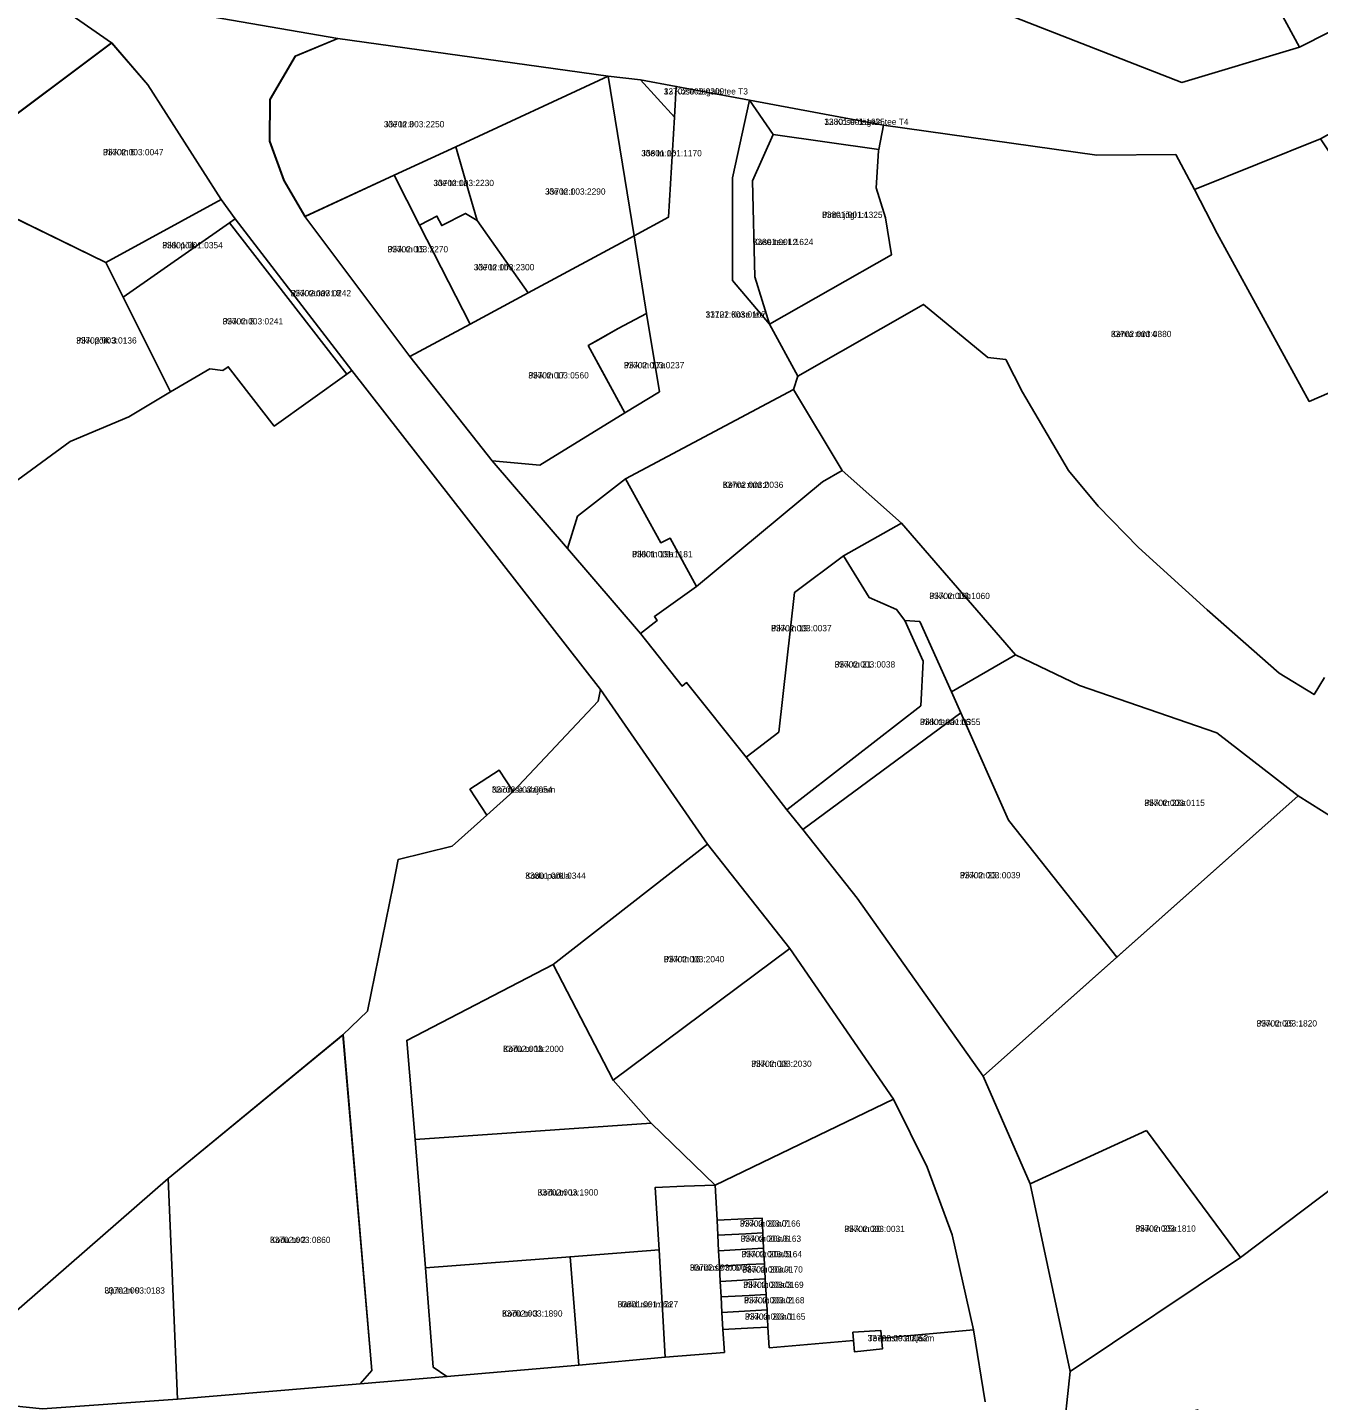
# Model space of a CAD drawing. Extents: x 551583 to 585220, y 6539942 to 6568852.
# Drawn here: x 566505.1 to 566814.5, y 6561149.5 to 6561478.7 of the extents above; entities that cross this region are included whole.
import ezdxf

# ---------------------------------------------------------------- set-up
doc = ezdxf.new("R2010")
doc.units = 0
for name, color, linetype in [('L_AADRESS', 7, 'Continuous'), ('PIIR', 7, 'Continuous'), ('TUNNUS', 7, 'Continuous')]:
    doc.layers.add(name, color=color, linetype=linetype)

msp = doc.modelspace()

# ---------------------------------------------------------------- linework, layer by layer
at = {"layer": 'PIIR'}
for points in [[(566791.18, 6561508.65), (566842.94, 6561542.25), (566867.01, 6561508.04), (566866.2, 6561503.29), (566839.93, 6561486.97), (566838.87, 6561488.68), (566809.96, 6561473.95)], [(566765.56, 6561529.79), (566776.67, 6561535.03), (566779.22, 6561530.74), (566791.18, 6561508.65), (566809.96, 6561473.95), (566781.7, 6561465.52), (566741.82, 6561481.07), (566731.29, 6561513.47)], [(566373.31, 6561508.62), (566505.33, 6561488.91), (566525.21, 6561475.01), (566494.84, 6561452.29), (566498.01, 6561445.37), (566497.1, 6561435.34), (566491.17, 6561435.81), (566484.69, 6561436.37), (566485.75, 6561446.39), (566479.83, 6561446.85), (566479.41, 6561443.1), (566466.6, 6561444.48), (566465.78, 6561437.06), (566427.68, 6561430.79), (566384.18, 6561428.7), (566375.88, 6561481.71), (566373.35, 6561504.49)], [(566579.42, 6561476.07), (566644.26, 6561466.97), (566607.74, 6561450.09), (566592.92, 6561443.25), (566571.62, 6561433.4), (566566.56, 6561442.03), (566563.14, 6561451.42), (566563.2, 6561461.42), (566569.28, 6561471.83)], [(566525.27, 6561475), (566533.92, 6561464.91), (566551.45, 6561437.4), (566523.81, 6561422.34), (566497.12, 6561435.35), (566498.05, 6561445.36), (566494.86, 6561452.26)], [(566607.74, 6561450.09), (566644.26, 6561466.97), (566650.48, 6561428.75), (566625.05, 6561415.05), (566612.84, 6561432.38), (566610.95, 6561438.97)], [(566644.26, 6561466.97), (566651.97, 6561466.15), (566660.11, 6561457.14), (566658.66, 6561433.18), (566650.48, 6561428.75)], [(566651.97, 6561466.15), (566660.57, 6561464.53), (566660.11, 6561457.14)], [(566634.52, 6561353.75), (566616.46, 6561374.76), (566627.86, 6561373.76), (566648.25, 6561386.29), (566656.51, 6561391.36), (566653.46, 6561410.12), (566650.48, 6561428.75), (566658.66, 6561433.18), (566660.11, 6561457.14), (566660.57, 6561464.53), (566678.07, 6561461.27), (566674, 6561442.65), (566674, 6561417.99), (566682.88, 6561407.58), (566689.67, 6561395.08), (566688.67, 6561391.93), (566648.38, 6561370.48), (566636.89, 6561361.49)], [(566678.07, 6561461.27), (566683.77, 6561453.02), (566678.86, 6561441.88), (566679.37, 6561418.92), (566682.88, 6561407.58), (566674, 6561417.99), (566674, 6561442.65)], [(566678.07, 6561461.27), (566710.22, 6561455.27), (566709.08, 6561449.39), (566683.77, 6561453.02)], [(566712.14, 6561424.15), (566682.88, 6561407.58), (566679.37, 6561418.92), (566678.86, 6561441.88), (566683.77, 6561453.02), (566709.08, 6561449.39), (566709.02, 6561449.07), (566708.45, 6561440.2), (566710.73, 6561433.05)], [(566592.92, 6561443.25), (566607.74, 6561450.09), (566610.95, 6561438.97), (566612.84, 6561432.38), (566610.01, 6561434.1), (566604.35, 6561431.2), (566603.19, 6561433.46), (566601.37, 6561432.52), (566599.02, 6561431.32)], [(566784.73, 6561439.81), (566814.94, 6561452), (566845.09, 6561406.59), (566817.08, 6561391.11), (566812.26, 6561389.03), (566790.24, 6561429.29)], [(566571.57, 6561433.4), (566592.92, 6561443.25), (566599.02, 6561431.32), (566611.17, 6561407.59), (566596.73, 6561399.83)], [(566527.97, 6561414.06), (566523.81, 6561422.34), (566551.45, 6561437.4), (566554.82, 6561432.81), (566553.47, 6561431.87)], [(566494.11, 6561409.47), (566497.1, 6561435.34), (566523.81, 6561422.34), (566527.97, 6561414.06), (566539.33, 6561391.32), (566529.37, 6561385.33), (566515.26, 6561379.42), (566501.54, 6561369.35)], [(566611.17, 6561407.59), (566599.02, 6561431.32), (566601.37, 6561432.52), (566603.19, 6561433.46), (566604.35, 6561431.2), (566610.01, 6561434.1), (566612.84, 6561432.38), (566625.05, 6561415.05)], [(566527.97, 6561414.06), (566553.47, 6561431.87), (566581.62, 6561395.6), (566564.22, 6561383.11), (566553.16, 6561397.34), (566551.88, 6561396.45), (566548.73, 6561396.87), (566539.33, 6561391.32)], [(566554.82, 6561432.81), (566582.77, 6561396.43), (566581.62, 6561395.6), (566553.47, 6561431.87)], [(566596.73, 6561399.83), (566611.17, 6561407.59), (566625.05, 6561415.05), (566650.48, 6561428.75), (566653.46, 6561410.12), (566646.67, 6561406.48), (566639.48, 6561402.43), (566648.25, 6561386.29), (566627.86, 6561373.76), (566616.46, 6561374.76)], [(566653.46, 6561410.12), (566656.51, 6561391.36), (566648.25, 6561386.29), (566643.23, 6561395.53), (566639.48, 6561402.43), (566641.89, 6561403.79), (566646.67, 6561406.48)], [(566688.67, 6561391.93), (566700.29, 6561372.46), (566695.58, 6561369.74), (566665.42, 6561344.67), (566659.13, 6561356.24), (566656.83, 6561355.14), (566648.38, 6561370.48)], [(566655.94, 6561336.48), (566655.31, 6561337.45), (566665.42, 6561344.67), (566695.58, 6561369.74), (566700.29, 6561372.46), (566714.58, 6561359.84), (566700.62, 6561352.02), (566688.93, 6561343.26), (566685.16, 6561309.77), (566677.33, 6561303.75), (566663.04, 6561321.63), (566661.95, 6561320.78), (566651.99, 6561333.42)], [(566634.52, 6561353.75), (566636.89, 6561361.49), (566648.38, 6561370.48), (566656.83, 6561355.14), (566659.13, 6561356.24), (566665.42, 6561344.67), (566655.31, 6561337.45), (566655.94, 6561336.48), (566651.99, 6561333.42)], [(566715.32, 6561336.51), (566713.35, 6561339.16), (566706.76, 6561342.04), (566700.62, 6561352.02), (566714.58, 6561359.84), (566741.83, 6561328.31), (566726.54, 6561319.38), (566718.91, 6561336.29)], [(566685.16, 6561309.77), (566688.93, 6561343.26), (566700.62, 6561352.02), (566706.76, 6561342.04), (566713.35, 6561339.16), (566715.32, 6561336.51), (566719.7, 6561326.75), (566719.18, 6561316.1), (566687.04, 6561291.15), (566677.33, 6561303.75)], [(566719.7, 6561326.75), (566715.32, 6561336.51), (566718.91, 6561336.29), (566726.54, 6561319.38), (566728.75, 6561314.4), (566690.91, 6561286.38), (566687.04, 6561291.15), (566719.18, 6561316.1)], [(566741.83, 6561328.31), (566757.19, 6561320.97), (566790.11, 6561309.55), (566809.58, 6561294.52), (566766.16, 6561255.81), (566757.22, 6561267.12), (566740.2, 6561288.65), (566728.75, 6561314.4), (566726.54, 6561319.38)], [(566641.85, 6561317.19), (566642.41, 6561319.99), (566668.05, 6561282.88), (566631.09, 6561254.05), (566595.96, 6561235.85), (566597.95, 6561212.08), (566600.42, 6561181.31), (566602.32, 6561157.52), (566605.58, 6561155.28), (566584.81, 6561153.57), (566587.62, 6561156.75), (566580.67, 6561237.22), (566586.54, 6561242.9), (566592.72, 6561273.06), (566593.91, 6561279.23), (566606.86, 6561282.43), (566615.13, 6561289.83), (566621.43, 6561295.54)], [(566728.75, 6561314.4), (566740.2, 6561288.65), (566757.22, 6561267.12), (566766.16, 6561255.81), (566734.14, 6561227.25), (566703.94, 6561269.96), (566690.91, 6561286.38)], [(566618.14, 6561300.63), (566621.43, 6561295.54), (566615.13, 6561289.83), (566611.1, 6561296.08)], [(566773.29, 6561214.3), (566745.37, 6561201.46), (566734.14, 6561227.25), (566809.58, 6561294.52), (566817.97, 6561289.18), (566836.97, 6561261.57), (566850.55, 6561242.08), (566857.57, 6561225.02), (566837.25, 6561215.15), (566795.8, 6561183.85)], [(566631.09, 6561254.05), (566668.05, 6561282.88), (566687.78, 6561257.9), (566645.4, 6561226.31)], [(566654.54, 6561216.06), (566645.4, 6561226.31), (566687.78, 6561257.9), (566712.64, 6561221.78), (566669.86, 6561201.15)], [(566595.96, 6561235.85), (566631.09, 6561254.05), (566645.4, 6561226.31), (566654.54, 6561216.06), (566597.95, 6561212.08)], [(566580.68, 6561237.22), (566587.62, 6561156.75), (566584.81, 6561153.57), (566541, 6561149.83), (566538.74, 6561202.78)], [(566754.97, 6561156.5), (566795.8, 6561183.85), (566837.25, 6561215.15), (566857.57, 6561225.02), (566866.03, 6561205.42), (566886.02, 6561186.2), (566900.8, 6561177.15), (566829.99, 6561104.3), (566800.56, 6561133.37), (566785.57, 6561147.3), (566753.17, 6561139.22)], [(566712.64, 6561221.78), (566720.67, 6561205.49), (566726.72, 6561189.28), (566731.83, 6561166.51), (566709.74, 6561164.51), (566709.59, 6561166.29), (566702.91, 6561165.88), (566703.07, 6561163.94), (566682.84, 6561162.18), (566682.54, 6561167.13), (566682.31, 6561171.27), (566682.1, 6561174.96), (566681.89, 6561178.69), (566681.69, 6561182.34), (566681.48, 6561186.02), (566681.28, 6561189.73), (566681.13, 6561193.27), (566677.02, 6561193.07), (566670.34, 6561192.76), (566669.86, 6561201.15)], [(566654.54, 6561216.06), (566669.86, 6561201.15), (566662.49, 6561200.88), (566655.52, 6561200.61), (566656.42, 6561185.66), (566635.11, 6561184.01), (566600.42, 6561181.31), (566597.95, 6561212.08)], [(566773.29, 6561214.3), (566795.8, 6561183.85), (566754.97, 6561156.5), (566745.37, 6561201.46)], [(566483.53, 6561154.66), (566538.74, 6561202.78), (566541, 6561149.83), (566508.62, 6561147.55), (566495.35, 6561148.9)], [(566656.42, 6561185.66), (566655.52, 6561200.61), (566662.49, 6561200.88), (566669.86, 6561201.15), (566670.34, 6561192.76), (566670.49, 6561189.14), (566670.69, 6561185.43), (566670.89, 6561181.75), (566671.09, 6561178.09), (566671.3, 6561174.37), (566671.5, 6561170.67), (566671.73, 6561166.54), (566672.1, 6561161.05), (566657.91, 6561159.89)], [(566670.34, 6561192.76), (566677.02, 6561193.07), (566681.13, 6561193.27), (566681.28, 6561189.73), (566677.22, 6561189.51), (566670.49, 6561189.14)], [(566670.49, 6561189.14), (566677.22, 6561189.51), (566681.28, 6561189.73), (566681.48, 6561186.02), (566677.42, 6561185.8), (566670.69, 6561185.43)], [(566602.32, 6561157.52), (566600.42, 6561181.31), (566635.11, 6561184.01), (566637.18, 6561157.97), (566605.58, 6561155.28)], [(566657.91, 6561159.89), (566637.18, 6561157.97), (566635.11, 6561184.01), (566656.42, 6561185.66)], [(566670.69, 6561185.43), (566677.42, 6561185.8), (566681.48, 6561186.02), (566681.69, 6561182.34), (566677.62, 6561182.12), (566670.89, 6561181.75)], [(566670.89, 6561181.75), (566677.62, 6561182.12), (566681.69, 6561182.34), (566681.89, 6561178.69), (566677.82, 6561178.46), (566671.09, 6561178.09)], [(566671.09, 6561178.09), (566677.82, 6561178.46), (566681.89, 6561178.69), (566682.1, 6561174.96), (566678.03, 6561174.74), (566671.3, 6561174.37)], [(566671.3, 6561174.37), (566678.03, 6561174.74), (566682.1, 6561174.96), (566682.31, 6561171.27), (566678.23, 6561171.04), (566671.5, 6561170.67)], [(566671.5, 6561170.67), (566678.23, 6561171.04), (566682.31, 6561171.27), (566682.54, 6561167.13), (566679.04, 6561166.94), (566671.73, 6561166.54)], [(566709.59, 6561166.29), (566709.74, 6561164.51), (566709.96, 6561161.92), (566703.3, 6561161.18), (566703.07, 6561163.94), (566702.91, 6561165.88)]]:
    msp.add_lwpolyline(points, close=True, dxfattribs=at)
for points in [[(566871.51, 6561490.84), (566868.9, 6561478.35), (566851.2, 6561471.97), (566814.94, 6561452), (566784.73, 6561439.81), (566780.27, 6561448.19), (566761.37, 6561448.1), (566710.22, 6561455.27), (566678.07, 6561461.27), (566660.57, 6561464.53), (566651.97, 6561466.15), (566644.26, 6561466.97), (566579.42, 6561476.07), (566505.33, 6561488.91)], [(566734.56, 6561149.23), (566731.83, 6561166.51), (566726.72, 6561189.28), (566720.67, 6561205.49), (566712.64, 6561221.78), (566687.78, 6561257.9), (566668.05, 6561282.88), (566642.41, 6561319.99), (566582.77, 6561396.43), (566554.82, 6561432.81), (566551.45, 6561437.4), (566533.92, 6561464.92), (566525.21, 6561475.01), (566505.33, 6561488.91), (566579.42, 6561476.07), (566569.23, 6561471.82), (566563.15, 6561461.42), (566563.09, 6561451.42), (566566.51, 6561442.03), (566571.57, 6561433.4), (566596.73, 6561399.83), (566616.46, 6561374.76), (566634.52, 6561353.75), (566651.99, 6561333.42), (566661.95, 6561320.78), (566663.04, 6561321.63), (566677.33, 6561303.75), (566687.04, 6561291.15), (566690.91, 6561286.38), (566703.94, 6561269.96), (566734.14, 6561227.25), (566745.37, 6561201.46), (566754.97, 6561156.5), (566753.17, 6561139.22)], [(566741.82, 6561481.07), (566781.7, 6561465.52), (566809.96, 6561473.95), (566838.87, 6561488.68)], [(566815.92, 6561322.84), (566813.42, 6561318.76), (566805.03, 6561323.92), (566787.81, 6561339.11), (566771.37, 6561354.05), (566761.68, 6561363.89), (566754.56, 6561372.49), (566743.55, 6561391.29), (566739.54, 6561399.08), (566735.24, 6561399.59), (566719.83, 6561412.27), (566689.67, 6561395.08), (566682.88, 6561407.58), (566712.14, 6561424.15), (566710.73, 6561433.05), (566708.45, 6561440.2), (566709.02, 6561449.07), (566709.08, 6561449.39), (566710.22, 6561455.27), (566761.37, 6561448.1), (566780.27, 6561448.19), (566784.73, 6561439.81), (566790.24, 6561429.29), (566812.26, 6561389.03), (566817.08, 6561391.11)], [(566817.97, 6561289.18), (566809.58, 6561294.52), (566790.11, 6561309.55), (566757.19, 6561320.97), (566741.83, 6561328.31), (566714.58, 6561359.84), (566700.29, 6561372.46), (566688.67, 6561391.93), (566689.67, 6561395.08), (566719.83, 6561412.27), (566735.24, 6561399.59), (566739.54, 6561399.08), (566743.55, 6561391.29), (566754.56, 6561372.49), (566761.68, 6561363.89), (566771.37, 6561354.05), (566787.81, 6561339.11), (566805.03, 6561323.92), (566813.42, 6561318.76), (566815.92, 6561322.84)], [(566501.54, 6561369.35), (566515.26, 6561379.42), (566529.37, 6561385.33), (566539.33, 6561391.32), (566548.73, 6561396.87), (566551.88, 6561396.45), (566553.16, 6561397.34), (566564.22, 6561383.11), (566581.62, 6561395.6), (566582.77, 6561396.43), (566642.41, 6561319.99), (566641.85, 6561317.19), (566621.43, 6561295.54), (566618.14, 6561300.63), (566611.1, 6561296.08), (566615.13, 6561289.83), (566606.86, 6561282.43), (566593.91, 6561279.23), (566592.72, 6561273.06), (566586.54, 6561242.9), (566580.67, 6561237.22), (566538.74, 6561202.78), (566483.53, 6561154.66)], [(566508.62, 6561147.55), (566541, 6561149.83), (566584.81, 6561153.57), (566605.58, 6561155.28), (566637.18, 6561157.97), (566657.91, 6561159.89), (566672.1, 6561161.05), (566671.73, 6561166.54), (566679.04, 6561166.94), (566682.54, 6561167.13), (566682.84, 6561162.18), (566703.07, 6561163.94), (566703.3, 6561161.18), (566709.96, 6561161.92), (566709.74, 6561164.51), (566731.83, 6561166.51), (566734.56, 6561149.23)]]:
    msp.add_lwpolyline(points, dxfattribs=at)

# ---------------------------------------------------------------- texts
at = {"layer": 'L_AADRESS'}
for s, p in [('12 Kose-Jägala tee T3', (566657.55, 6561462.61)), ('Jõe tn 3', (566590.47, 6561454.74)), ('12 Kose-Jägala tee T4', (566696.04, 6561455.33)), ('Pikk tn 6', (566523.16, 6561448.04)), ('Jõe tn 1c', (566652.18, 6561447.79)), ('Jõe tn 1a', (566602.36, 6561440.65)), ('Jõe tn 1', (566629.11, 6561438.6)), ('Pirita jõgi L4', (566695.5, 6561433.03)), ('Pikk põik', (566537.36, 6561425.73)), ('Kose tee L2', (566678.89, 6561426.51)), ('Pikk tn 15', (566591.37, 6561424.76)), ('Jõe tn 1b', (566612.04, 6561420.46)), ('Pikk tänav L8', (566568.12, 6561414.25)), ('11121 Kose tee', (566667.58, 6561409.14)), ('Pikk tn 8', (566551.82, 6561407.49)), ('Pikk põik 3', (566516.72, 6561402.91)), ('Kehra mnt 4', (566764.74, 6561404.45)), ('Pikk tn 17a', (566647.99, 6561396.97)), ('Pikk tn 17', (566625.09, 6561394.54)), ('Kehra mnt 2', (566671.71, 6561368.3)), ('Pikk tn 19a', (566649.97, 6561351.68)), ('Pikk tn 19b', (566721.22, 6561341.66)), ('Pikk tn 19', (566683.29, 6561333.92)), ('Pikk tn 21', (566698.52, 6561325.25)), ('Pikk tänav L6', (566718.97, 6561311.45)), ('Nooruse alajaam', (566616.37, 6561295.23)), ('Pikk tn 23a', (566772.75, 6561292.06)), ('Kodu parkla', (566624.36, 6561274.6)), ('Pikk tn 23', (566728.53, 6561274.71)), ('Pikk tn 16', (566657.57, 6561254.59)), ('Pikk tn 25', (566799.63, 6561239.19)), ('Kodu tn 1b', (566619.05, 6561233.07)), ('Pikk tn 18', (566678.51, 6561229.52)), ('Kodu tn 1a', (566627.33, 6561198.68)), ('Pikk tn 20a/7', (566675.81, 6561191.21)), ('Pikk tn 20', (566700.84, 6561189.92)), ('Pikk tn 25a', (566770.58, 6561190.01)), ('Kodu tn 2', (566563.18, 6561187.29)), ('Pikk tn 20a/6', (566675.98, 6561187.58)), ('Pikk tn 20a/5', (566676.19, 6561183.88)), ('Hariduse tn 6', (566663.81, 6561180.65)), ('Pikk tn 20a/4', (566676.39, 6561180.21)), ('Ujula tn 9', (566523.49, 6561175.17)), ('Pikk tn 20a/3', (566676.59, 6561176.53)), ('Hariduse tn 6a', (566646.51, 6561171.86)), ('Pikk tn 20a/2', (566676.8, 6561172.82)), ('Kodu tn 3', (566618.8, 6561169.65)), ('Pikk tn 20a/1', (566677.02, 6561168.9)), ('Teenuste alajaam', (566706.45, 6561163.74))]:
    msp.add_text(s, height=1.5, dxfattribs=at).set_placement(p)
at = {"layer": 'TUNNUS'}
for s, p in [('33702:003:0209', (566657.55, 6561462.61)), ('33702:003:2250', (566590.47, 6561454.74)), ('33801:001:1625', (566696.04, 6561455.33)), ('33702:003:0047', (566523.16, 6561448.04)), ('33801:001:1170', (566652.18, 6561447.79)), ('33702:003:2230', (566602.36, 6561440.65)), ('33702:003:2290', (566629.11, 6561438.6)), ('33801:001:1325', (566695.5, 6561433.03)), ('33801:001:0354', (566537.36, 6561425.73)), ('33801:001:1624', (566678.89, 6561426.51)), ('33702:003:2270', (566591.37, 6561424.76)), ('33702:003:2300', (566612.04, 6561420.46)), ('33702:003:0242', (566568.12, 6561414.25)), ('33702:003:0107', (566667.58, 6561409.14)), ('33702:003:0241', (566551.82, 6561407.49)), ('33702:003:0136', (566516.72, 6561402.91)), ('33702:003:0880', (566764.74, 6561404.45)), ('33702:003:0237', (566647.99, 6561396.97)), ('33702:003:0560', (566625.09, 6561394.54)), ('33702:003:0036', (566671.71, 6561368.3)), ('33801:001:1181', (566649.97, 6561351.68)), ('33702:003:1060', (566721.22, 6561341.66)), ('33702:003:0037', (566683.29, 6561333.92)), ('33702:003:0038', (566698.52, 6561325.25)), ('33801:001:0355', (566718.97, 6561311.45)), ('33702:003:0054', (566616.37, 6561295.23)), ('33702:003:0115', (566772.75, 6561292.06)), ('33801:001:0344', (566624.36, 6561274.6)), ('33702:003:0039', (566728.53, 6561274.71)), ('33702:003:2040', (566657.57, 6561254.59)), ('33702:003:1820', (566799.63, 6561239.19)), ('33702:003:2000', (566619.05, 6561233.07)), ('33702:003:2030', (566678.51, 6561229.52)), ('33702:003:1900', (566627.33, 6561198.68)), ('33702:003:0166', (566675.81, 6561191.21)), ('33702:003:0031', (566700.84, 6561189.92)), ('33702:003:1810', (566770.58, 6561190.01)), ('33702:003:0860', (566563.18, 6561187.29)), ('33702:003:0163', (566675.98, 6561187.58)), ('33702:003:0164', (566676.19, 6561183.88)), ('33702:003:0003', (566663.81, 6561180.65)), ('33702:003:0170', (566676.39, 6561180.21)), ('33702:003:0183', (566523.49, 6561175.17)), ('33702:003:0169', (566676.59, 6561176.53)), ('33801:001:1227', (566646.51, 6561171.86)), ('33702:003:0168', (566676.8, 6561172.82)), ('33702:003:1890', (566618.8, 6561169.65)), ('33702:003:0165', (566677.02, 6561168.9)), ('33702:003:0052', (566706.45, 6561163.74))]:
    msp.add_text(s, height=1.5, dxfattribs=at).set_placement(p)

doc.saveas('drawing.dxf')
